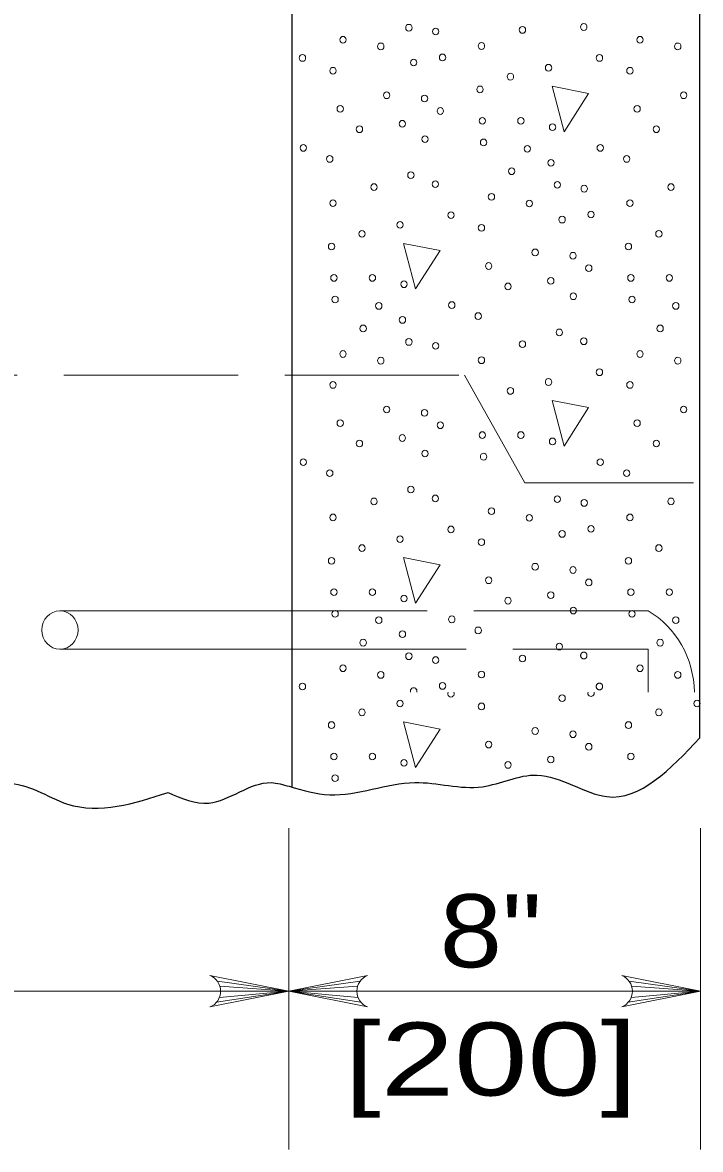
# Model space of a CAD drawing. Extents: x 1083.1 to 1117.1, y 697.4 to 719.4.
# Drawn here: x 1098.084 to 1099.532, y 710.545 to 712.953 of the extents above; entities that cross this region are included whole.
import ezdxf
from ezdxf.enums import TextEntityAlignment as Align

# ---------------------------------------------------------------- set-up
doc = ezdxf.new("R2010")
doc.units = 0
doc.header["$LTSCALE"] = 0.062
doc.linetypes.add('LONG_DASHED', pattern=[7.5, 6, -1.5])
doc.layers.add('1', color=7, linetype='Continuous', lineweight=13)

msp = doc.modelspace()

# ---------------------------------------------------------------- linework, layer by layer
at = {"layer": '1', "lineweight": 25}
msp.add_line((1098.65942, 715.33867), (1098.65942, 711.32025), dxfattribs=at)
at = {"layer": '1', "linetype": 'LONG_DASHED'}
for p, q in [((1094.39633, 712.19967), (1099.02808, 712.19967)), ((1099.42025, 711.69567), (1098.65133, 711.69567)), ((1098.65942, 711.61367), (1099.42025, 711.61367)), ((1099.42025, 711.61367), (1099.42025, 711.52217))]:
    msp.add_line(p, q, dxfattribs=at)
at = {"layer": '1'}
for p, q in [((1098.65133, 711.69567), (1098.16383, 711.69567)), ((1098.16383, 711.61367), (1098.65942, 711.61367)), ((1098.65258, 711.23125), (1098.65258, 710.54458)), ((1099.53217, 711.23125), (1099.53217, 710.54458)), ((1098.50033, 710.90408), (1098.65258, 710.88275)), ((1098.50542, 710.8935), (1098.65258, 710.88275)), ((1098.80492, 710.90408), (1098.65258, 710.88275)), ((1098.79975, 710.8935), (1098.65258, 710.88275)), ((1099.37992, 710.90408), (1099.53217, 710.88275)), ((1099.38508, 710.8935), (1099.53217, 710.88275)), ((1098.3885, 710.88275), (1094.811, 710.88275)), ((1098.65258, 710.88275), (1098.3885, 710.88275)), ((1098.4985, 710.85917), (1098.65258, 710.88275)), ((1098.50433, 710.86908), (1098.65258, 710.88275)), ((1098.507, 710.88275), (1098.65258, 710.88275)), ((1098.79817, 710.88275), (1098.65258, 710.88275)), ((1098.80083, 710.86908), (1098.65258, 710.88275)), ((1098.80667, 710.85917), (1098.65258, 710.88275)), ((1099.37808, 710.85917), (1099.53217, 710.88275)), ((1099.38392, 710.86908), (1099.53217, 710.88275)), ((1099.38667, 710.88275), (1099.53217, 710.88275))]:
    msp.add_line(p, q, dxfattribs=at)
at = {"layer": '1', "lineweight": 25}
msp.add_lwpolyline([(1099.53092, 711.424), (1099.53092, 711.52217), (1099.53092, 715.85275)], dxfattribs=at)
at = {"layer": '1'}
for points in [[(1099.21525, 712.81692), (1099.24092, 712.71958), (1099.29317, 712.80167)], [(1098.89808, 712.48108), (1098.92375, 712.38367), (1098.97592, 712.46583)], [(1099.21525, 712.14517), (1099.24092, 712.04792), (1099.29317, 712.13008)], [(1098.89808, 711.80942), (1098.92375, 711.71208), (1098.97592, 711.79425)], [(1098.89808, 711.45825), (1098.92375, 711.361), (1098.97592, 711.44308)]]:
    msp.add_lwpolyline(points, close=True, dxfattribs=at)
at = {"layer": '1', "linetype": 'LONG_DASHED'}
msp.add_lwpolyline([(1099.02808, 712.19967), (1099.15725, 711.969), (1099.5175, 711.969)], dxfattribs=at)
at = {"layer": '1'}
for points in [[(1098.48433, 710.84908), (1098.65258, 710.88275), (1098.48433, 710.91642)], [(1098.82083, 710.84908), (1098.65258, 710.88275), (1098.82083, 710.91642)], [(1099.364, 710.84908), (1099.53217, 710.88275), (1099.364, 710.91642)], [(1099.53217, 710.88275), (1099.29983, 710.88275), (1098.65258, 710.88275)]]:
    msp.add_lwpolyline(points, dxfattribs=at)
for centre, start, end in [((1098.47079, 710.88278), 292.08605, 67.91218), ((1098.8344, 710.88278), 112.08782, 247.91395), ((1099.3504, 710.88278), 292.08605, 67.91218)]:
    msp.add_arc(centre, 0.03631, start, end, dxfattribs=at)
for centre, major_axis in [((1098.90928, 712.94196), (0, 0.00718)), ((1098.96664, 712.93373), (0, 0.00718)), ((1099.15194, 712.93715), (0, 0.00718)), ((1099.283, 712.94347), (0, 0.00718)), ((1098.7685, 712.91627), (0, 0.00718)), ((1099.4029, 712.91627), (0, 0.00718)), ((1098.84928, 712.90205), (0, 0.00718)), ((1099.06429, 712.90289), (0, 0.00718)), ((1099.48368, 712.90205), (0, 0.00718)), ((1098.68196, 712.87726), (0, 0.00718)), ((1098.91949, 712.86758), (0, 0.00718)), ((1098.98118, 712.87849), (0, 0.00718)), ((1099.31636, 712.87726), (0, 0.00718)), ((1098.74709, 712.85006), (0, 0.00718)), ((1099.1262, 712.83735), (0, 0.00718)), ((1099.20761, 712.85638), (0, 0.00718)), ((1099.38149, 712.85006), (0, 0.00718)), ((1099.06117, 712.81015), (0, 0.00718)), ((1098.86186, 712.7975), (0, 0.00718)), ((1098.9427, 712.7905), (0, 0.00718)), ((1099.49626, 712.7975), (0, 0.00718)), ((1098.76253, 712.76845), (0, 0.00718)), ((1098.97637, 712.76392), (0, 0.00718)), ((1099.39693, 712.76845), (0, 0.00718)), ((1098.89527, 712.73672), (0, 0.00718)), ((1099.0663, 712.74304), (0, 0.00718)), ((1099.14856, 712.74304), (0, 0.00718)), ((1098.80366, 712.72491), (0, 0.00718)), ((1099.21618, 712.72944), (0, 0.00718)), ((1099.43806, 712.72491), (0, 0.00718)), ((1098.94354, 712.70375), (0, 0.00718)), ((1099.06884, 712.69681), (0, 0.00718)), ((1098.6837, 712.685), (0, 0.00718)), ((1099.16225, 712.68321), (0, 0.00718)), ((1099.3181, 712.685), (0, 0.00718)), ((1098.74022, 712.66143), (0, 0.00718)), ((1099.21274, 712.65326), (0, 0.00718)), ((1099.37462, 712.66143), (0, 0.00718)), ((1098.91357, 712.62668), (0, 0.00718)), ((1099.12879, 712.63513), (0, 0.00718)), ((1098.83474, 712.60132), (0, 0.00718)), ((1098.9658, 712.60765), (0, 0.00718)), ((1099.22648, 712.60614), (0, 0.00718)), ((1099.28385, 712.59791), (0, 0.00718)), ((1099.46914, 712.60132), (0, 0.00718)), ((1099.0857, 712.58045), (0, 0.00718)), ((1098.74709, 712.56707), (0, 0.00718)), ((1099.16648, 712.56623), (0, 0.00718)), ((1099.38149, 712.56707), (0, 0.00718)), ((1098.89041, 712.52056), (0, 0.00718)), ((1098.99916, 712.54143), (0, 0.00718)), ((1099.23669, 712.53175), (0, 0.00718)), ((1099.29838, 712.54266), (0, 0.00718)), ((1098.809, 712.50153), (0, 0.00718)), ((1099.06429, 712.51423), (0, 0.00718)), ((1099.4434, 712.50153), (0, 0.00718)), ((1098.74397, 712.47432), (0, 0.00718)), ((1099.37837, 712.47432), (0, 0.00718)), ((1099.17906, 712.46168), (0, 0.00718)), ((1099.2599, 712.45468), (0, 0.00718)), ((1099.07973, 712.43263), (0, 0.00718)), ((1099.29357, 712.42809), (0, 0.00718)), ((1098.7491, 712.40722), (0, 0.00718)), ((1098.83136, 712.40722), (0, 0.00718)), ((1099.21247, 712.40089), (0, 0.00718)), ((1099.3835, 712.40722), (0, 0.00718)), ((1099.46576, 712.40722), (0, 0.00718)), ((1098.89897, 712.39361), (0, 0.00718)), ((1099.12086, 712.38908), (0, 0.00718)), ((1098.75163, 712.36098), (0, 0.00718)), ((1099.26074, 712.36792), (0, 0.00718)), ((1099.38604, 712.36098), (0, 0.00718)), ((1098.84505, 712.34738), (0, 0.00718)), ((1099.0009, 712.34917), (0, 0.00718)), ((1099.47945, 712.34738), (0, 0.00718)), ((1098.89554, 712.31744), (0, 0.00718)), ((1099.05742, 712.32561), (0, 0.00718)), ((1098.81159, 712.2993), (0, 0.00718)), ((1099.23077, 712.29085), (0, 0.00718)), ((1099.44599, 712.2993), (0, 0.00718)), ((1098.90928, 712.27031), (0, 0.00718)), ((1098.96664, 712.26208), (0, 0.00718)), ((1099.15194, 712.2655), (0, 0.00718)), ((1099.283, 712.27182), (0, 0.00718)), ((1098.7685, 712.24462), (0, 0.00718)), ((1099.06429, 712.23124), (0, 0.00718)), ((1099.4029, 712.24462), (0, 0.00718)), ((1098.84928, 712.2304), (0, 0.00718)), ((1099.48368, 712.2304), (0, 0.00718)), ((1099.20761, 712.18473), (0, 0.00718)), ((1099.31636, 712.20561), (0, 0.00718)), ((1098.74709, 712.17841), (0, 0.00718)), ((1099.1262, 712.1657), (0, 0.00718)), ((1099.38149, 712.17841), (0, 0.00718)), ((1098.86186, 712.12585), (0, 0.00718)), ((1098.9427, 712.11885), (0, 0.00718)), ((1099.49626, 712.12585), (0, 0.00718)), ((1098.76253, 712.0968), (0, 0.00718)), ((1098.97637, 712.09227), (0, 0.00718)), ((1099.39693, 712.0968), (0, 0.00718)), ((1098.89527, 712.06507), (0, 0.00718)), ((1099.0663, 712.07139), (0, 0.00718)), ((1099.14856, 712.07139), (0, 0.00718)), ((1098.80366, 712.05326), (0, 0.00718)), ((1099.21618, 712.05779), (0, 0.00718)), ((1099.43806, 712.05326), (0, 0.00718)), ((1098.94354, 712.0321), (0, 0.00718)), ((1099.06884, 712.02516), (0, 0.00718)), ((1098.6837, 712.01335), (0, 0.00718)), ((1098.74022, 711.98979), (0, 0.00718)), ((1099.3181, 712.01335), (0, 0.00718)), ((1099.37462, 711.98979), (0, 0.00718)), ((1098.91357, 711.95503), (0, 0.00718)), ((1098.83474, 711.92967), (0, 0.00718)), ((1098.9658, 711.936), (0, 0.00718)), ((1099.22648, 711.93449), (0, 0.00718)), ((1099.28385, 711.92626), (0, 0.00718)), ((1099.46914, 711.92967), (0, 0.00718)), ((1098.74709, 711.89542), (0, 0.00718)), ((1099.0857, 711.9088), (0, 0.00718)), ((1099.16648, 711.89458), (0, 0.00718)), ((1099.38149, 711.89542), (0, 0.00718)), ((1098.99916, 711.86978), (0, 0.00718)), ((1099.29838, 711.87102), (0, 0.00718)), ((1098.89041, 711.84891), (0, 0.00718)), ((1099.23669, 711.8601), (0, 0.00718)), ((1098.809, 711.82988), (0, 0.00718)), ((1099.06429, 711.84258), (0, 0.00718)), ((1099.4434, 711.82988), (0, 0.00718)), ((1098.74397, 711.80268), (0, 0.00718)), ((1099.37837, 711.80268), (0, 0.00718)), ((1099.17906, 711.79003), (0, 0.00718)), ((1099.2599, 711.78303), (0, 0.00718)), ((1099.07973, 711.76098), (0, 0.00718)), ((1099.29357, 711.75644), (0, 0.00718)), ((1098.7491, 711.73557), (0, 0.00718)), ((1098.83136, 711.73557), (0, 0.00718)), ((1099.21247, 711.72924), (0, 0.00718)), ((1099.3835, 711.73557), (0, 0.00718)), ((1099.46576, 711.73557), (0, 0.00718)), ((1098.89897, 711.72197), (0, 0.00718)), ((1099.12086, 711.71743), (0, 0.00718)), ((1098.16384, 711.65468), (0, -0.041)), ((1098.75163, 711.68933), (0, 0.00718)), ((1099.0009, 711.67752), (0, 0.00718)), ((1099.26074, 711.69627), (0, 0.00718)), ((1099.38604, 711.68933), (0, 0.00718)), ((1098.84505, 711.67573), (0, 0.00718)), ((1099.05742, 711.65396), (0, 0.00718)), ((1099.47945, 711.67573), (0, 0.00718)), ((1098.89554, 711.64579), (0, 0.00718)), ((1098.81159, 711.62765), (0, 0.00718)), ((1099.23077, 711.6192), (0, 0.00718)), ((1099.44599, 711.62765), (0, 0.00718)), ((1098.90928, 711.59866), (0, 0.00718)), ((1098.96664, 711.59043), (0, 0.00718)), ((1099.15194, 711.59385), (0, 0.00718)), ((1098.7685, 711.57297), (0, 0.00718)), ((1098.84928, 711.55875), (0, 0.00718)), ((1099.06429, 711.55959), (0, 0.00718)), ((1099.4029, 711.57297), (0, 0.00718)), ((1099.48368, 711.55875), (0, 0.00718)), ((1098.68196, 711.53396), (0, 0.00718)), ((1098.98118, 711.53519), (0, 0.00718)), ((1099.23669, 711.50898), (0, 0.00718)), ((1098.89041, 711.49778), (0, 0.00718)), ((1099.06429, 711.49146), (0, 0.00718)), ((1099.52481, 711.49778), (0, 0.00718)), ((1098.809, 711.47875), (0, 0.00718)), ((1099.4434, 711.47875), (0, 0.00718)), ((1098.74397, 711.45155), (0, 0.00718)), ((1099.17906, 711.4389), (0, 0.00718)), ((1099.37837, 711.45155), (0, 0.00718)), ((1099.2599, 711.43191), (0, 0.00718)), ((1099.07973, 711.40985), (0, 0.00718)), ((1099.29357, 711.40532), (0, 0.00718)), ((1098.7491, 711.38444), (0, 0.00718)), ((1098.83136, 711.38444), (0, 0.00718)), ((1098.89897, 711.37084), (0, 0.00718)), ((1099.12086, 711.36631), (0, 0.00718)), ((1099.21247, 711.37812), (0, 0.00718)), ((1099.3835, 711.38444), (0, 0.00718)), ((1098.75163, 711.33821), (0, 0.00718))]:
    msp.add_ellipse(centre, major_axis=major_axis, ratio=0.944544, dxfattribs=at)
at = {"layer": '1', "linetype": 'LONG_DASHED'}
msp.add_ellipse((1099.32758, 711.5179), major_axis=(0, -0.20306), ratio=0.944544, start_param=1.5918753, end_param=2.6372404, dxfattribs=at)
for centre in [(1099.283, 711.60017), (1099.31636, 711.53396)]:
    msp.add_ellipse(centre, major_axis=(0, 0.00718), ratio=0.944544, dxfattribs=at)
at = {"layer": '1'}
for centre, start_param, end_param in [((1098.91949, 711.52428), 4.4160941, 8.1502766), ((1098.99916, 711.51866), 1.0586317, 5.2245535), ((1099.29838, 711.51989), 1.2465299, 5.0366554)]:
    msp.add_ellipse(centre, major_axis=(0, 0.00718), ratio=0.944544, start_param=start_param, end_param=end_param, dxfattribs=at)
at = {"layer": '1', "lineweight": 25}
for points in [[(1098.65325, 711.32067), (1098.74008, 711.30267), (1098.92183, 711.32892), (1099.06625, 711.31983), (1099.18275, 711.34475), (1099.33183, 711.29858), (1099.53092, 711.424)], [(1094.7835, 711.34008), (1094.7925, 711.34258), (1094.91825, 711.31), (1095.0525, 711.33592), (1095.16525, 711.29067), (1095.31992, 711.33525), (1095.43267, 711.29475), (1095.54733, 711.344), (1095.66008, 711.30558), (1095.76175, 711.33333), (1095.87442, 711.30167), (1095.98533, 711.32358), (1096.0925, 711.29675), (1096.20533, 711.34408), (1096.35342, 711.30192), (1096.48108, 711.33567), (1096.58267, 711.301), (1096.77, 711.32808), (1096.90883, 711.31517), (1097.00767, 711.33408), (1097.1185, 711.29467), (1097.235, 711.33317), (1097.3645, 711.29575), (1097.54817, 711.318), (1097.66092, 711.299), (1097.81183, 711.325), (1097.90033, 711.28158), (1098.05042, 711.32617), (1098.17992, 711.28283), (1098.39475, 711.30733)], [(1098.39475, 711.30733), (1098.482, 711.285), (1098.61517, 711.3285), (1098.65325, 711.32067)]]:
    msp.add_spline(points, degree=3, dxfattribs=at)

# ---------------------------------------------------------------- texts
at = {"layer": '1'}
for s, width, p in [('8"', 1.15, (1099.08425, 710.93392)), ('[200]', 1.35, (1099.08425, 710.65983))]:
    msp.add_text(s, height=0.156, dxfattribs=dict(at, width=width)).set_placement(p, align=Align.CENTER)

doc.saveas('drawing.dxf')
